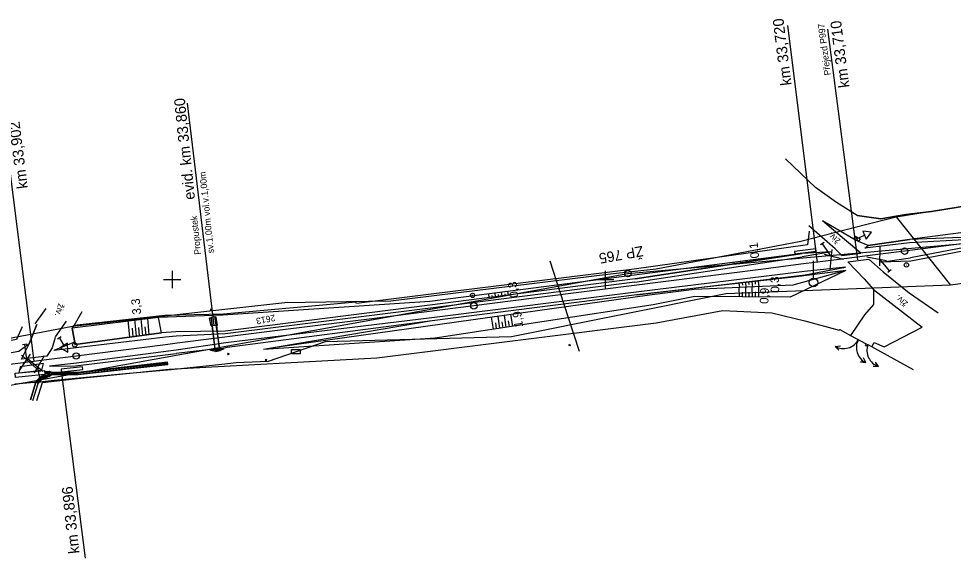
# Model space of a CAD drawing. Extents: x -805011 to -803920, y -1150790 to -1150234.
# Drawn here: x -804735.5 to -804519.6, y -1150564.4 to -1150439.8 of the extents above; entities that cross this region are included whole.
import ezdxf

# ---------------------------------------------------------------- set-up
doc = ezdxf.new("R2010")
doc.units = 0
for name, color, linetype in [('0381KM032-037P - Vrstva 1', 7, 'Continuous'), ('0381KM032-037P - Vrstva 12', 7, 'Continuous'), ('0381KM032-037P - Vrstva 13', 7, 'Continuous'), ('0381KM032-037P - Vrstva 17', 7, 'Continuous'), ('0381KM032-037P - Vrstva 19', 7, 'Continuous'), ('0381KM032-037P - Vrstva 25', 7, 'Continuous'), ('0381KM032-037P - Vrstva 36', 7, 'Continuous'), ('0381KM032-037P - Vrstva 4', 7, 'Continuous'), ('0381KM032-037P - Vrstva 43', 7, 'Continuous'), ('0381KM032-037P - Vrstva 48', 7, 'Continuous'), ('0381KM032-037P - Vrstva 49', 7, 'Continuous'), ('0381KM032-037P - Vrstva 51', 7, 'Continuous'), ('0381KM032-037P - Vrstva 55', 7, 'Continuous'), ('0381KM032-037P - Vrstva 57', 7, 'Continuous'), ('0381KM032-037P - Vrstva 7', 7, 'Continuous'), ('0381KM032-037P - Vrstva 9', 7, 'Continuous'), ('hran DP - hran DP', 7, 'Continuous'), ('krizky_1000 - Vrstva 1', 7, 'Continuous'), ('vyt_sit - polygon', 7, 'Continuous'), ('vyt_sit - stávající', 7, 'Continuous')]:
    doc.layers.add(name, color=color, linetype=linetype)

msp = doc.modelspace()

# ---------------------------------------------------------------- linework, layer by layer
at = {"layer": '0381KM032-037P - Vrstva 1'}
msp.add_lwpolyline([(-804485.9, -1150487.74), (-804508.11, -1150490.55), (-804529.67, -1150493.3), (-804537.63, -1150494.31), (-804546.61, -1150495.46), (-804554.2, -1150496.42), (-804564.05, -1150497.67), (-804586.01, -1150500.48), (-804607.92, -1150503.26), (-804630.35, -1150506.11), (-804652.65, -1150508.9), (-804675.7, -1150511.78), (-804698.85, -1150514.71), (-804701.61, -1150515.06), (-804722.18, -1150517.67), (-804729.05, -1150518.54), (-804735.1, -1150519.31), (-804744.56, -1150520.5), (-804767.65, -1150523.46), (-804791, -1150526.42)], dxfattribs=at)
at = {"layer": '0381KM032-037P - Vrstva 12'}
for p, q in [((-804542.27, -1150490.03), (-804542.27, -1150490.03)), ((-804541.15, -1150490.64), (-804541.15, -1150490.64))]:
    msp.add_line(p, q, dxfattribs=at)
msp.add_lwpolyline([(-804542.6, -1150490.68), (-804542.27, -1150490.03), (-804541.15, -1150490.64), (-804541.52, -1150491.26), (-804542.6, -1150490.68), (-804542.27, -1150490.03), (-804541.15, -1150490.64), (-804541.52, -1150491.26)], dxfattribs=at)
at = {"layer": '0381KM032-037P - Vrstva 13'}
for points in [[(-804703.22, -1150508.8), (-804723.12, -1150511.26), (-804722.46, -1150514.99), (-804702.53, -1150512.35), (-804703.22, -1150508.8)], [(-804732.2, -1150527.92), (-804730.97, -1150524.01), (-804730.13, -1150523.06), (-804728.33, -1150522.36), (-804727.9, -1150521.95), (-804721.78, -1150521.96), (-804701.01, -1150519.63), (-804701.03, -1150519.46), (-804701.1, -1150519.22), (-804701.1, -1150519.05)], [(-804731.12, -1150523.92), (-804730.21, -1150522.94), (-804728.39, -1150522.25), (-804727.91, -1150521.81), (-804721.79, -1150521.85), (-804701.03, -1150519.46)], [(-804729.45, -1150521.32), (-804728.46, -1150521.31), (-804727.91, -1150521.54), (-804721.8, -1150521.59), (-804701.1, -1150519.22)], [(-804729.38, -1150521.22), (-804728.48, -1150521.2), (-804727.92, -1150521.41), (-804721.8, -1150521.43), (-804701.1, -1150519.05)], [(-804732.74, -1150527.78), (-804731.51, -1150523.73), (-804730.41, -1150522.51), (-804728.49, -1150521.85), (-804728.25, -1150521.76), (-804728.53, -1150521.71), (-804729.44, -1150521.68)], [(-804731.32, -1150523.78), (-804730.35, -1150522.68), (-804728.48, -1150521.99), (-804728.25, -1150521.76), (-804728.5, -1150521.58), (-804729.42, -1150521.57)], [(-804729.38, -1150521.22), (-804729.45, -1150521.32), (-804729.42, -1150521.57), (-804729.44, -1150521.68)], [(-804731.51, -1150523.73), (-804731.32, -1150523.78), (-804731.12, -1150523.92), (-804730.97, -1150524.01)]]:
    msp.add_lwpolyline(points, dxfattribs=at)
at = {"layer": '0381KM032-037P - Vrstva 17'}
for p, q in [((-804731.66, -1150510.27), (-804729.1, -1150506.73)), ((-804726.96, -1150513.28), (-804724.46, -1150509.62)), ((-804553.92, -1150509.55), (-804545.93, -1150511.73)), ((-804546.89, -1150515.44), (-804546.02, -1150516.35)), ((-804539.31, -1150515.02), (-804528.85, -1150520.76)), ((-804539.82, -1150519.19), (-804541.07, -1150518.98)), ((-804538.15, -1150520.02), (-804536.89, -1150520.06)), ((-804536.89, -1150520.06), (-804538.15, -1150520.02)), ((-804536.89, -1150520.06), (-804537.59, -1150519.06))]:
    msp.add_line(p, q, dxfattribs=at)
for points in [[(-804368.54, -1150462.33), (-804374.42, -1150462.03), (-804388.45, -1150464.13), (-804427.08, -1150469.25), (-804429.72, -1150469.73), (-804431.75, -1150470.1), (-804437.24, -1150471.08), (-804446.96, -1150472.02), (-804473.97, -1150476), (-804503.76, -1150480.94), (-804524.61, -1150484.28), (-804530.6, -1150485.02), (-804536.33, -1150485.99), (-804541.81, -1150485.21), (-804546.58, -1150482.25), (-804551.41, -1150478.74), (-804558.4, -1150472.14)], [(-804552.89, -1150488.84), (-804553.29, -1150492.03), (-804593.3, -1150497.6), (-804640.86, -1150503.43), (-804657.42, -1150505.51), (-804657.62, -1150505.23), (-804688.14, -1150507.97), (-804701.71, -1150508.32), (-804722.68, -1150510.59), (-804720.85, -1150507.4)], [(-804731.29, -1150527.98), (-804729.95, -1150523.81), (-804721.9, -1150522.89), (-804700.75, -1150520.73), (-804652.77, -1150518.11), (-804588.21, -1150510.02), (-804572.8, -1150507.15), (-804561.55, -1150507.7), (-804553.92, -1150509.55)], [(-804734.71, -1150510.96), (-804735.96, -1150513.84), (-804741.77, -1150514.83), (-804760.36, -1150517.2), (-804793.92, -1150520.9)], [(-804545.93, -1150511.73), (-804545.83, -1150511.58), (-804543.33, -1150512.91)], [(-804546.02, -1150516.35), (-804546.89, -1150515.44), (-804545.68, -1150515.29)], [(-804539.92, -1150515.23), (-804539.73, -1150514.83), (-804539.31, -1150515.02)], [(-804539.92, -1150515.23), (-804539.5, -1150515.43), (-804539.31, -1150515.02)], [(-804541.07, -1150518.98), (-804539.82, -1150519.19), (-804540.38, -1150518.1)]]:
    msp.add_lwpolyline(points, dxfattribs=at)
for centre, start, end in [((-804544.94, -1150512.13), 239.5292, 333.049), ((-804538.17, -1150515.73), 150.9796, 244.4995), ((-804535.73, -1150516.4), 158.9316, 252.4515)]:
    msp.add_arc(centre, 3.83, start, end, dxfattribs=at)
at = {"layer": '0381KM032-037P - Vrstva 19'}
for p, q in [((-804690.3, -1150510.66), (-804696.47, -1150459.27)), ((-804690.02, -1150516.61), (-804690.96, -1150508.7)), ((-804688.92, -1150516.37), (-804690.16, -1150508.54)), ((-804690.09, -1150516.25), (-804690.83, -1150510.72)), ((-804689.77, -1150510.59), (-804689.19, -1150516.28)), ((-804690.02, -1150516.61), (-804688.92, -1150516.37))]:
    msp.add_line(p, q, dxfattribs=at)
for points in [[(-804689.58, -1150510.57), (-804689.77, -1150510.59), (-804690.83, -1150510.72), (-804691.04, -1150510.74), (-804691.4, -1150508.85), (-804691.12, -1150508.86), (-804690.83, -1150510.72)], [(-804691.12, -1150508.86), (-804690.96, -1150508.7), (-804690.59, -1150508.62), (-804690.16, -1150508.54), (-804690.08, -1150508.63)], [(-804689.58, -1150510.57), (-804689.88, -1150508.68), (-804690.08, -1150508.63), (-804689.77, -1150510.59)], [(-804688.16, -1150516.11), (-804688.92, -1150516.37), (-804689.19, -1150516.28), (-804690.09, -1150516.25), (-804690.02, -1150516.61), (-804691.14, -1150516.38)]]:
    msp.add_lwpolyline(points, dxfattribs=at)
msp.add_lwpolyline([(-804688.22, -1150515.92), (-804688.16, -1150516.11), (-804691.14, -1150516.38), (-804691.19, -1150516.18)], close=True, dxfattribs=at)
at = {"layer": '0381KM032-037P - Vrstva 25'}
for points in [[(-804612.83, -1150495.66), (-804610.41, -1150503.1), (-804608.55, -1150508.81), (-804606.04, -1150516.52)], [(-804672.5, -1150517.17), (-804672.5, -1150516.17), (-804670.5, -1150516.17), (-804670.5, -1150517.17), (-804672.5, -1150517.17)]]:
    msp.add_lwpolyline(points, dxfattribs=at)
at = {"layer": '0381KM032-037P - Vrstva 36'}
for p, q in [((-804551.87, -1150499.69), (-804551.87, -1150495.69)), ((-804551.87, -1150500.69), (-804551.87, -1150500.69))]:
    msp.add_line(p, q, dxfattribs=at)
msp.add_circle((-804551.87, -1150500.69), 1, dxfattribs=at)
at = {"layer": '0381KM032-037P - Vrstva 4'}
for p, q in [((-804541.64, -1150495.45), (-804548.57, -1150442.16)), ((-804738.68, -1150465.82), (-804731.99, -1150518.9)), ((-804515.79, -1150490.21), (-804529.7, -1150490.74)), ((-804549.45, -1150491.46), (-804550.27, -1150492.03)), ((-804549.86, -1150491.75), (-804547.86, -1150494.62)), ((-804529.7, -1150491.57), (-804540.01, -1150492.74)), ((-804536.6, -1150496.85), (-804536.52, -1150492.24)), ((-804515.61, -1150490.8), (-804529.7, -1150491.57)), ((-804515.43, -1150492.3), (-804529.48, -1150494.97)), ((-804593.11, -1150499.86), (-804554.49, -1150494.02)), ((-804547.76, -1150493.63), (-804554.49, -1150494.02)), ((-804547.76, -1150493.63), (-804554.48, -1150494.77)), ((-804544.88, -1150495.41), (-804549.34, -1150494.25)), ((-804547.69, -1150493.1), (-804548.16, -1150497.69)), ((-804537.63, -1150494.31), (-804546.61, -1150495.46)), ((-804515.37, -1150493.06), (-804529.38, -1150495.79)), ((-804593.19, -1150500.62), (-804554.48, -1150494.77)), ((-804539.6, -1150494.79), (-804535.05, -1150495.58)), ((-804534.33, -1150498.02), (-804536.56, -1150495.33)), ((-804536.34, -1150495.99), (-804529.48, -1150494.97)), ((-804529.38, -1150495.79), (-804536.34, -1150495.99)), ((-804553.94, -1150498.18), (-804592.89, -1150502.96)), ((-804544.49, -1150497.19), (-804553.94, -1150498.18)), ((-804553.83, -1150498.96), (-804544.49, -1150497.19)), ((-804534.71, -1150498.34), (-804533.94, -1150497.7)), ((-804592.67, -1150503.55), (-804553.83, -1150498.96)), ((-804699.22, -1150512.12), (-804702.53, -1150512.35)), ((-804733.62, -1150514.94), (-804734.61, -1150515.06)), ((-804734.11, -1150515), (-804733.68, -1150518.47)), ((-804691.19, -1150516.18), (-804699.14, -1150517.12)), ((-804688.22, -1150515.92), (-804691.19, -1150516.18)), ((-804732.83, -1150517.21), (-804735.37, -1150521.05)), ((-804731.4, -1150520.55), (-804734.81, -1150517.46)), ((-804733.43, -1150518.25), (-804729.87, -1150521.17)), ((-804731.84, -1150521.52), (-804729.49, -1150517.55)), ((-804729.05, -1150518.54), (-804735.1, -1150519.31)), ((-804730.44, -1150523.66), (-804731.05, -1150520.21)), ((-804730.93, -1150523.75), (-804729.95, -1150523.57))]:
    msp.add_line(p, q, dxfattribs=at)
for points in [[(-804540.01, -1150492.74), (-804539.3, -1150492.14), (-804529.7, -1150490.74)], [(-804593.11, -1150499.86), (-804640.49, -1150505.94), (-804687.8, -1150511.91), (-804699.22, -1150512.12)], [(-804593.19, -1150500.62), (-804640.38, -1150506.6), (-804687.82, -1150512.54), (-804699.1, -1150513.12)], [(-804592.89, -1150502.96), (-804640.05, -1150508.88), (-804687.61, -1150514.59), (-804699.07, -1150516.32)], [(-804592.67, -1150503.55), (-804639.94, -1150509.55), (-804687.3, -1150515.71), (-804688.22, -1150515.92)], [(-804699.1, -1150513.12), (-804701.6, -1150513.32), (-804727.4, -1150516.37)], [(-804702.53, -1150512.35), (-804722.46, -1150514.99), (-804722.57, -1150514.49)], [(-804722.57, -1150514.49), (-804727.4, -1150516.37)], [(-804699.07, -1150516.32), (-804722.12, -1150519.29), (-804728.4, -1150520.02), (-804722.36, -1150519.97), (-804699.14, -1150517.12)]]:
    msp.add_lwpolyline(points, dxfattribs=at)
at = {"layer": '0381KM032-037P - Vrstva 43'}
msp.add_lwpolyline([(-804736.33, -1150521.65), (-804729.5, -1150520.98), (-804729.45, -1150521.92), (-804736.22, -1150522.62)], close=True, dxfattribs=at)
at = {"layer": '0381KM032-037P - Vrstva 48'}
for p, q in [((-804570.19, -1150496.39), (-804570.24, -1150496.05)), ((-804569.44, -1150496.28), (-804569.47, -1150496.12)), ((-804568.7, -1150496.17), (-804568.75, -1150495.86)), ((-804567.96, -1150496.06), (-804567.98, -1150495.91)), ((-804567.22, -1150495.94), (-804567.26, -1150495.67)), ((-804566.48, -1150495.83), (-804566.5, -1150495.7)), ((-804565.74, -1150495.72), (-804565.77, -1150495.47)), ((-804569.12, -1150500.87), (-804569.01, -1150501.87)), ((-804568.38, -1150500.79), (-804568.32, -1150501.31)), ((-804567.63, -1150500.7), (-804567.51, -1150501.8)), ((-804566.89, -1150500.62), (-804566.82, -1150501.19)), ((-804566.14, -1150500.53), (-804566.01, -1150501.74)), ((-804565.4, -1150500.45), (-804565.33, -1150501.07)), ((-804564.65, -1150500.36), (-804564.5, -1150501.67)), ((-804625.33, -1150504), (-804625.43, -1150503.17)), ((-804623.84, -1150503.8), (-804623.94, -1150502.98)), ((-804622.35, -1150503.61), (-804622.46, -1150502.79)), ((-804569.02, -1150504), (-804569.05, -1150501.87)), ((-804568.27, -1150504.01), (-804568.28, -1150502.92)), ((-804567.52, -1150504.01), (-804567.55, -1150501.8)), ((-804566.77, -1150504.02), (-804566.78, -1150502.9)), ((-804566.02, -1150504.03), (-804566.05, -1150501.74)), ((-804565.26, -1150504.03), (-804565.28, -1150502.87)), ((-804564.51, -1150504.04), (-804564.55, -1150501.67)), ((-804626.81, -1150504.19), (-804626.92, -1150503.36)), ((-804626.07, -1150504.09), (-804626.12, -1150503.68)), ((-804624.58, -1150503.9), (-804624.63, -1150503.49)), ((-804623.09, -1150503.71), (-804623.15, -1150503.3)), ((-804709.78, -1150513.31), (-804710.17, -1150509.4)), ((-804708.29, -1150513.12), (-804708.68, -1150509.26)), ((-804706.81, -1150512.92), (-804707.19, -1150509.11)), ((-804705.32, -1150512.72), (-804705.69, -1150508.97)), ((-804625.83, -1150511.5), (-804626.24, -1150508.72)), ((-804624.35, -1150511.27), (-804624.75, -1150508.52)), ((-804622.87, -1150511.04), (-804623.27, -1150508.31)), ((-804622.12, -1150510.93), (-804622.33, -1150509.57)), ((-804621.38, -1150510.81), (-804621.78, -1150508.1)), ((-804709.04, -1150513.21), (-804709.23, -1150511.27)), ((-804707.55, -1150513.02), (-804707.74, -1150511.1)), ((-804706.06, -1150512.82), (-804706.25, -1150510.93)), ((-804625.09, -1150511.38), (-804625.29, -1150510)), ((-804623.61, -1150511.16), (-804623.81, -1150509.78))]:
    msp.add_line(p, q, dxfattribs=at)
at = {"layer": '0381KM032-037P - Vrstva 49'}
for p, q in [((-804554.49, -1150494.02), (-804593.11, -1150499.86)), ((-804544.42, -1150497.94), (-804556.53, -1150499.44)), ((-804690.87, -1150506.79), (-804691.22, -1150507.14)), ((-804691.22, -1150506.79), (-804690.87, -1150507.14)), ((-804608.49, -1150515.04), (-804608.04, -1150515.25)), ((-804608.15, -1150514.92), (-804608.37, -1150515.37)), ((-804686.9, -1150517.05), (-804687.25, -1150517.41)), ((-804687.25, -1150517.05), (-804686.9, -1150517.41)), ((-804678.19, -1150518.41), (-804678.54, -1150518.76)), ((-804678.54, -1150518.41), (-804678.19, -1150518.76))]:
    msp.add_line(p, q, dxfattribs=at)
for points in [[(-804541.81, -1150485.21), (-804536.33, -1150485.99), (-804530.6, -1150485.02), (-804524.61, -1150484.28), (-804503.76, -1150480.94), (-804473.97, -1150476), (-804446.96, -1150472.02), (-804437.24, -1150471.08), (-804431.75, -1150470.1), (-804429.72, -1150469.73), (-804427.08, -1150469.25), (-804388.45, -1150464.13), (-804374.42, -1150462.03), (-804368.54, -1150462.33), (-804346.87, -1150460.56), (-804338.71, -1150460.38), (-804328.85, -1150461.67), (-804323.06, -1150462.29), (-804320.34, -1150463.27)], [(-804529.7, -1150490.74), (-804539.3, -1150492.14), (-804541.52, -1150491.26), (-804542.6, -1150490.68), (-804549.8, -1150486.44)], [(-804516.1, -1150489.01), (-804529.7, -1150490.74)], [(-804554.49, -1150494.02), (-804593.21, -1150499.01), (-804640.53, -1150505.12), (-804688.31, -1150508.22), (-804703.24, -1150508.74), (-804722.68, -1150510.59)], [(-804544.42, -1150497.94), (-804556.65, -1150501.33), (-804579.48, -1150502.32), (-804589.81, -1150503.62), (-804675.11, -1150515.57), (-804678.92, -1150516.15)], [(-804544.42, -1150497.94), (-804557.28, -1150504.11), (-804579.29, -1150503.91), (-804588.92, -1150505.83), (-804639.29, -1150513.56), (-804678.92, -1150516.15)], [(-804593.11, -1150499.86), (-804640.49, -1150505.94), (-804687.8, -1150511.91), (-804699.22, -1150512.12)], [(-804556.53, -1150499.44), (-804592.67, -1150503.55), (-804639.94, -1150509.55), (-804678.92, -1150516.15)], [(-804731.33, -1150510.42), (-804733.06, -1150514.89), (-804735.43, -1150516.61), (-804744.9, -1150518.34), (-804767.83, -1150521.26), (-804794.61, -1150523.51)], [(-804722.46, -1150514.99), (-804723.12, -1150511.26), (-804722.68, -1150510.59)], [(-804699.22, -1150512.12), (-804702.53, -1150512.35), (-804722.46, -1150514.99)], [(-804690.02, -1150516.61), (-804688.92, -1150516.37), (-804689.47, -1150516.35), (-804690.02, -1150516.61)]]:
    msp.add_lwpolyline(points, dxfattribs=at)
at = {"layer": '0381KM032-037P - Vrstva 51'}
for p, q in [((-804546.9, -1150492.89), (-804552.96, -1150487.64)), ((-804544.77, -1150490.77), (-804549.8, -1150486.44)), ((-804542.14, -1150490.12), (-804541.74, -1150491.03)), ((-804545.36, -1150494.48), (-804546.9, -1150492.89)), ((-804540.22, -1150499.84), (-804543.98, -1150495.94)), ((-804725.64, -1150513.28), (-804726.5, -1150513.8))]:
    msp.add_line(p, q, dxfattribs=at)
for points in [[(-804541.94, -1150490.58), (-804540.11, -1150489.77), (-804539.71, -1150490.69), (-804538.51, -1150489.07), (-804540.51, -1150488.86), (-804540.11, -1150489.77)], [(-804545.36, -1150494.48), (-804540.93, -1150493.94), (-804544.77, -1150490.77)], [(-804543.98, -1150495.94), (-804539.14, -1150495.31), (-804535.78, -1150498.25)], [(-804535.78, -1150498.25), (-804529.76, -1150503.07), (-804523.07, -1150507.67)], [(-804540.22, -1150499.84), (-804538.01, -1150502.34), (-804526.8, -1150511.03)], [(-804538.01, -1150502.34), (-804538.01, -1150505.79), (-804540.15, -1150508.19), (-804543.33, -1150512.91), (-804539.73, -1150514.83)], [(-804727.06, -1150513.38), (-804727.78, -1150515.77), (-804729, -1150517.7), (-804734.83, -1150518.42), (-804733.06, -1150514.89), (-804731.33, -1150510.42)], [(-804538.41, -1150515.52), (-804537.89, -1150514.57), (-804535.54, -1150515.57), (-804526.8, -1150511.03)], [(-804726.07, -1150513.54), (-804725.04, -1150515.25), (-804725.9, -1150515.77), (-804724.14, -1150516.75), (-804724.18, -1150514.73), (-804725.04, -1150515.25)], [(-804729.45, -1150521.92), (-804730.41, -1150522.51), (-804731.51, -1150523.73), (-804732.74, -1150527.78)]]:
    msp.add_lwpolyline(points, dxfattribs=at)
msp.add_lwpolyline([(-804730.11, -1150520.97), (-804729.76, -1150519.41), (-804735.16, -1150520.17), (-804735.48, -1150521.58)], close=True, dxfattribs=at)
at = {"layer": '0381KM032-037P - Vrstva 55'}
msp.add_line((-804532.83, -1150485.53), (-804520.26, -1150501.29), dxfattribs=at)
at = {"layer": '0381KM032-037P - Vrstva 7'}
for p, q in [((-804530.38, -1150496.64), (-804530.48, -1150496.66)), ((-804630.6, -1150503.66), (-804630.7, -1150503.68)), ((-804722.48, -1150515.11), (-804722.58, -1150515.12))]:
    msp.add_line(p, q, dxfattribs=at)
for centre, radius in [((-804530.84, -1150493.45), 0.75), ((-804530.43, -1150496.65), 0.5), ((-804630.65, -1150503.67), 0.5), ((-804630.34, -1150506.1), 0.75), ((-804722.53, -1150515.12), 0.5), ((-804722.2, -1150517.67), 0.75)]:
    msp.add_circle(centre, radius, dxfattribs=at)
at = {"layer": '0381KM032-037P - Vrstva 9'}
for p, q in [((-804550.95, -1150496.05), (-804557.83, -1150441.36)), ((-804551.35, -1150492.89), (-804551.42, -1150492.3)), ((-804551.35, -1150492.89), (-804556.31, -1150493.51)), ((-804556.31, -1150493.51), (-804556.24, -1150494.1)), ((-804556.24, -1150494.1), (-804551.28, -1150493.49)), ((-804551.28, -1150493.49), (-804551.35, -1150492.89)), ((-804720.72, -1150520.2), (-804725.69, -1150520.71)), ((-804720.66, -1150520.79), (-804720.72, -1150520.2)), ((-804725.69, -1150520.71), (-804725.63, -1150521.31)), ((-804725.66, -1150521.01), (-804720.15, -1150564.39)), ((-804725.63, -1150521.31), (-804720.66, -1150520.79)), ((-804725.63, -1150521.31), (-804725.57, -1150521.9))]:
    msp.add_line(p, q, dxfattribs=at)
at = {"layer": 'hran DP - hran DP'}
for p, q in [((-804532.83, -1150485.53), (-804473.24, -1150476.04)), ((-804539.55, -1150487.24), (-804532.83, -1150485.53)), ((-804554.84, -1150491.12), (-804539.55, -1150487.24)), ((-804574.54, -1150494.89), (-804554.84, -1150491.12)), ((-804588.25, -1150497.51), (-804574.54, -1150494.89)), ((-804477.16, -1150495.64), (-804520.26, -1150501.29)), ((-804621.33, -1150501.45), (-804598.8, -1150498.68)), ((-804598.8, -1150498.68), (-804588.25, -1150497.51)), ((-804649.49, -1150504.92), (-804634.52, -1150503.07)), ((-804634.52, -1150503.07), (-804621.33, -1150501.45)), ((-804537.98, -1150501.97), (-804572.18, -1150503.29)), ((-804532.2, -1150501.75), (-804537.98, -1150501.97)), ((-804520.26, -1150501.29), (-804532.2, -1150501.75)), ((-804688.55, -1150506.95), (-804674.03, -1150505.33)), ((-804674.03, -1150505.33), (-804659.84, -1150505.09)), ((-804659.84, -1150505.09), (-804649.49, -1150504.92)), ((-804572.18, -1150503.29), (-804621.63, -1150513.27)), ((-804723.03, -1150510.78), (-804688.55, -1150506.95)), ((-804747.72, -1150515.43), (-804723.03, -1150510.78)), ((-804621.63, -1150513.27), (-804664.68, -1150514.39)), ((-804664.68, -1150514.39), (-804677.85, -1150518.93)), ((-804688.56, -1150519.6), (-804700.23, -1150520.83)), ((-804685.22, -1150519.25), (-804688.56, -1150519.6)), ((-804677.85, -1150518.93), (-804685.22, -1150519.25)), ((-804710.79, -1150521.81), (-804727.28, -1150523.34)), ((-804700.23, -1150520.83), (-804710.79, -1150521.81)), ((-804729.97, -1150523.63), (-804736.36, -1150524.18)), ((-804727.28, -1150523.34), (-804729.97, -1150523.63))]:
    msp.add_line(p, q, dxfattribs=at)
at = {"layer": 'krizky_1000 - Vrstva 1'}
for points in [[(-804700, -1150498), (-804700, -1150502)], [(-804600, -1150498), (-804600, -1150502)], [(-804702, -1150500), (-804698, -1150500)], [(-804602, -1150500), (-804598, -1150500)]]:
    msp.add_lwpolyline(points, dxfattribs=at)
at = {"layer": 'vyt_sit - polygon'}
for p, q in [((-804594.75, -1150498.6), (-804444.16, -1150485.23)), ((-804740.83, -1150524.99), (-804594.75, -1150498.6))]:
    msp.add_line(p, q, dxfattribs=at)
at = {"layer": 'vyt_sit - stávající'}
msp.add_line((-804594.8, -1150498.6), (-804594.7, -1150498.6), dxfattribs=at)
msp.add_circle((-804594.75, -1150498.6), 0.756, dxfattribs=at)

# ---------------------------------------------------------------- texts
at = {"layer": '0381KM032-037P - Vrstva 19'}
for s, height, p in [('evid. km 33,860', 2.5, (-804694.74, -1150481.46)), ('sv.1,00m vol.v.1,00m', 1.5, (-804690.37, -1150493.89)), ('Propustek', 1.5, (-804693.36, -1150494.19))]:
    msp.add_text(s, height=height, rotation=95.8316, dxfattribs=at).set_placement(p)
at = {"layer": '0381KM032-037P - Vrstva 4'}
for s, height, rotation, p in [('km 33,710', 2.5, 97.2836, (-804543.58, -1150455.56)), ('Přejezd P997', 1.5, 97.2836, (-804547.9, -1150452.76)), ('km 33,902', 2.5, 97.1938, (-804733.36, -1150478.88))]:
    msp.add_text(s, height=height, rotation=rotation, dxfattribs=at).set_placement(p)
at = {"layer": '0381KM032-037P - Vrstva 48'}
for s, rotation, p in [('0,1', 96.0264, (-804564.42, -1150495.02)), ('0,3', 97.3526, (-804620.03, -1150504.07)), ('0,3', 91.5025, (-804559.78, -1150503.01)), ('0,9', 87.4636, (-804562.33, -1150505.67)), ('3,3', 95.4373, (-804707.19, -1150508.01)), ('1,9', 97.9771, (-804618.96, -1150510.9))]:
    msp.add_text(s, height=2, rotation=rotation, dxfattribs=at).set_placement(p)
at = {"layer": '0381KM032-037P - Vrstva 51'}
for rotation, p in [(139.2713, (-804545.56, -1150490.88)), (140.5584, (-804529.95, -1150505.32)), (253.3622, (-804726.29, -1150505.42))]:
    msp.add_text('živ.', height=1.5, rotation=rotation, dxfattribs=at).set_placement(p)
at = {"layer": '0381KM032-037P - Vrstva 57'}
msp.add_text('2613', height=1.5, rotation=191.1139, dxfattribs=at).set_placement((-804676.37, -1150508.07))
at = {"layer": '0381KM032-037P - Vrstva 9'}
for s, rotation, p in [('km 33,720', 97.0859, (-804556.94, -1150455.05)), ('km 33,896', 95.8904, (-804721.45, -1150563.2))]:
    msp.add_text(s, height=2.5, rotation=rotation, dxfattribs=at).set_placement(p)
at = {"layer": 'vyt_sit - stávající'}
msp.add_text('ŽP 765', height=2.4, rotation=190, dxfattribs=at).set_placement((-804591.41, -1150492.21))

doc.saveas('drawing.dxf')
